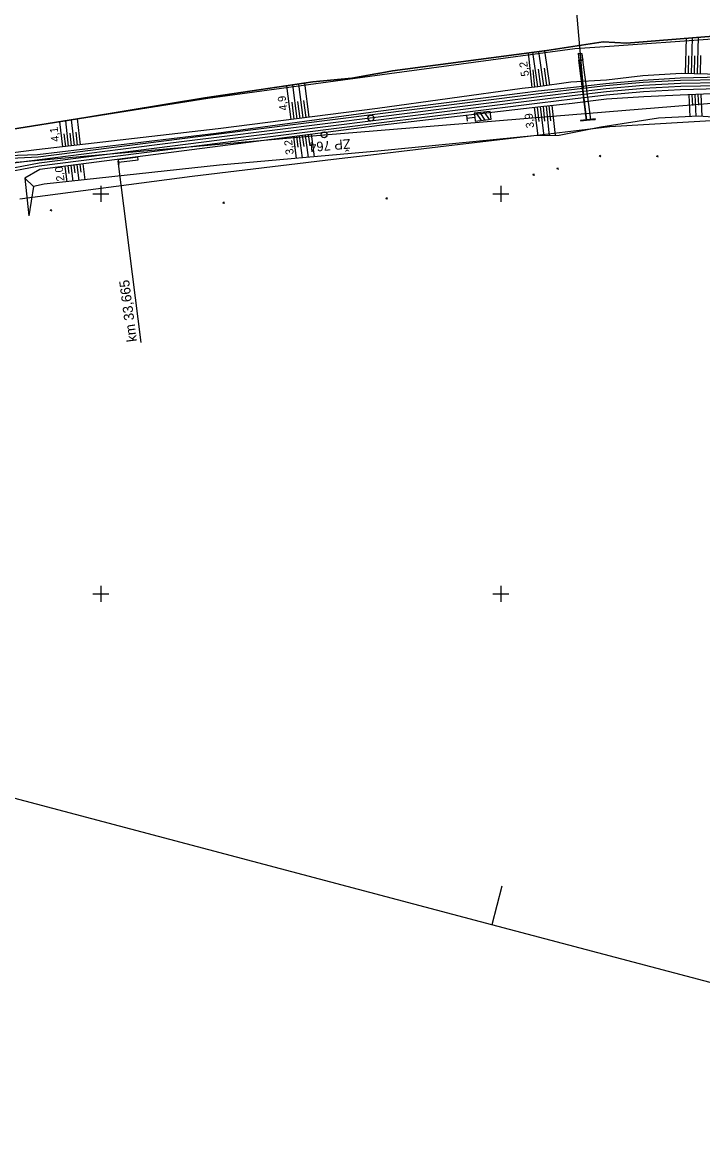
# Model space of a CAD drawing. Extents: x -805011 to -803920, y -1150790 to -1150234.
# Drawn here: x -804519.6 to -804349.5, y -1150736.4 to -1150457.1 of the extents above; entities that cross this region are included whole.
import ezdxf

# ---------------------------------------------------------------- set-up
doc = ezdxf.new("R2010")
doc.units = 0
for name, color, linetype in [('0381KM032-037P - Vrstva 1', 7, 'Continuous'), ('0381KM032-037P - Vrstva 17', 7, 'Continuous'), ('0381KM032-037P - Vrstva 19', 7, 'Continuous'), ('0381KM032-037P - Vrstva 4', 7, 'Continuous'), ('0381KM032-037P - Vrstva 48', 7, 'Continuous'), ('0381KM032-037P - Vrstva 49', 7, 'Continuous'), ('0381KM032-037P - Vrstva 7', 7, 'Continuous'), ('0381KM032-037P - Vrstva 9', 7, 'Continuous'), ('formát', 7, 'Continuous'), ('hran DP - hran DP', 7, 'Continuous'), ('krizky_1000 - Vrstva 1', 7, 'Continuous'), ('vyt_sit - polygon', 7, 'Continuous'), ('vyt_sit - stávající', 7, 'Continuous')]:
    doc.layers.add(name, color=color, linetype=linetype)

msp = doc.modelspace()

# ---------------------------------------------------------------- linework, layer by layer
at = {"layer": '0381KM032-037P - Vrstva 1'}
for points in [[(-804345.19, -1150472.22), (-804355.1, -1150472.39), (-804364.37, -1150472.93), (-804373.68, -1150473.77), (-804382.25, -1150474.73), (-804390.38, -1150475.71), (-804394.38, -1150476.22)], [(-804394.38, -1150476.22), (-804430.66, -1150480.81), (-804470.38, -1150485.81), (-804485.9, -1150487.74)], [(-804485.9, -1150487.74), (-804508.11, -1150490.55), (-804529.67, -1150493.3), (-804537.63, -1150494.31), (-804546.61, -1150495.46), (-804554.2, -1150496.42), (-804564.05, -1150497.67), (-804586.01, -1150500.48), (-804607.92, -1150503.26), (-804630.35, -1150506.11), (-804652.65, -1150508.9), (-804675.7, -1150511.78), (-804698.85, -1150514.71), (-804701.61, -1150515.06), (-804722.18, -1150517.67), (-804729.05, -1150518.54), (-804735.1, -1150519.31), (-804744.56, -1150520.5), (-804767.65, -1150523.46), (-804791, -1150526.42)]]:
    msp.add_lwpolyline(points, dxfattribs=at)
at = {"layer": '0381KM032-037P - Vrstva 17'}
for points in [[(-804368.54, -1150462.33), (-804374.42, -1150462.03), (-804388.45, -1150464.13), (-804427.08, -1150469.25), (-804429.72, -1150469.73), (-804431.75, -1150470.1), (-804437.24, -1150471.08), (-804446.96, -1150472.02), (-804473.97, -1150476), (-804503.76, -1150480.94), (-804524.61, -1150484.28), (-804530.6, -1150485.02), (-804536.33, -1150485.99), (-804541.81, -1150485.21), (-804546.58, -1150482.25), (-804551.41, -1150478.74), (-804558.4, -1150472.14)], [(-804328.85, -1150461.67), (-804338.71, -1150460.38), (-804346.87, -1150460.56), (-804368.54, -1150462.33)]]:
    msp.add_lwpolyline(points, dxfattribs=at)
at = {"layer": '0381KM032-037P - Vrstva 19'}
for p, q in [((-804384.94, -1150412.13), (-804379.37, -1150473.64)), ((-804380.55, -1150464.84), (-804380.55, -1150464.84)), ((-804378.59, -1150481.54), (-804380.47, -1150466.54)), ((-804380.44, -1150466.61), (-804378.59, -1150481.59)), ((-804379.54, -1150466.49), (-804379.54, -1150466.49)), ((-804379.54, -1150466.49), (-804377.61, -1150481.41)), ((-804378.59, -1150481.59), (-804377.64, -1150481.48))]:
    msp.add_line(p, q, dxfattribs=at)
for points in [[(-804380.55, -1150464.84), (-804380.57, -1150464.89), (-804380.47, -1150466.54)], [(-804380.44, -1150466.61), (-804380.55, -1150464.84), (-804379.8, -1150464.93), (-804379.51, -1150466.55)], [(-804379.8, -1150464.93), (-804379.76, -1150464.9), (-804379.54, -1150466.49)], [(-804379.51, -1150466.55), (-804379.54, -1150466.49), (-804380.47, -1150466.54), (-804380.44, -1150466.61), (-804379.51, -1150466.55)], [(-804379.54, -1150466.49), (-804380.47, -1150466.54), (-804380.47, -1150466.54)]]:
    msp.add_lwpolyline(points, dxfattribs=at)
for points in [[(-804380.55, -1150464.84), (-804380.55, -1150464.84)], [(-804378.59, -1150481.54), (-804377.61, -1150481.41), (-804377.64, -1150481.48), (-804376.42, -1150481.39), (-804376.29, -1150481.28), (-804380.1, -1150481.67), (-804380.08, -1150481.76), (-804378.59, -1150481.59)]]:
    msp.add_lwpolyline(points, close=True, dxfattribs=at)
at = {"layer": '0381KM032-037P - Vrstva 4'}
for p, q in [((-804515.79, -1150490.21), (-804529.7, -1150490.74)), ((-804515.61, -1150490.8), (-804529.7, -1150491.57)), ((-804515.43, -1150492.3), (-804529.48, -1150494.97)), ((-804515.43, -1150492.3), (-804515.43, -1150492.3)), ((-804515.37, -1150493.06), (-804529.38, -1150495.79)), ((-804515.37, -1150493.06), (-804515.37, -1150493.06))]:
    msp.add_line(p, q, dxfattribs=at)
for points in [[(-804225.7, -1150511.47), (-804233.93, -1150505.38), (-804241.84, -1150500.35), (-804251.18, -1150495.03), (-804260.27, -1150490.25), (-804271.39, -1150485.02), (-804282.1, -1150481.42), (-804291.28, -1150478.15), (-804302, -1150475.62), (-804311.22, -1150473.82), (-804320.47, -1150472.35), (-804331.17, -1150471.28), (-804341.36, -1150470.84), (-804345.11, -1150470.79), (-804355.15, -1150471.09), (-804364.49, -1150471.64), (-804373.72, -1150472.46), (-804382.56, -1150473.46), (-804390.64, -1150474.3), (-804394.58, -1150474.82), (-804430.68, -1150479.4), (-804471.16, -1150484.87), (-804515.79, -1150490.21)], [(-804222.47, -1150514.31), (-804225.93, -1150511.88), (-804233.81, -1150506.22), (-804242.12, -1150500.85), (-804250.57, -1150495.96), (-804260.44, -1150490.89), (-804271.28, -1150486.07), (-804282.21, -1150481.99), (-804291.28, -1150479.14), (-804302.11, -1150476.36), (-804311.33, -1150474.54), (-804320.55, -1150473.14), (-804330.83, -1150472.06), (-804341.5, -1150471.52), (-804345.16, -1150471.47), (-804355.1, -1150471.64), (-804364.39, -1150472.17), (-804373.73, -1150473.02), (-804382.33, -1150473.97), (-804390.45, -1150474.97), (-804394.45, -1150475.48), (-804430.79, -1150480.07), (-804470.48, -1150485.06), (-804515.61, -1150490.8)], [(-804223.37, -1150515.97), (-804226.85, -1150513.1), (-804234.67, -1150507.48), (-804242.93, -1150502.16), (-804251.31, -1150497.29), (-804261.13, -1150492.25), (-804271.85, -1150487.49), (-804282.71, -1150483.42), (-804291.73, -1150480.59), (-804302.46, -1150477.85), (-804311.66, -1150476.01), (-804320.71, -1150474.65), (-804330.94, -1150473.58), (-804341.55, -1150473.05), (-804345.16, -1150472.99), (-804355.02, -1150473.16), (-804364.28, -1150473.69), (-804373.57, -1150474.51), (-804382.12, -1150475.46), (-804390.26, -1150476.46), (-804394.25, -1150476.96), (-804430.61, -1150481.56), (-804470.33, -1150486.56), (-804515.43, -1150492.3)], [(-804235.83, -1150507.71), (-804243.11, -1150502.63), (-804252.43, -1150497.68), (-804261.4, -1150493.06), (-804272.11, -1150488.47), (-804283.06, -1150484.22), (-804291.82, -1150481.32), (-804302.89, -1150478.85), (-804311.92, -1150476.81), (-804320.92, -1150475.47), (-804331.06, -1150474.34), (-804341.56, -1150473.81), (-804345.45, -1150473.75), (-804355.04, -1150473.96), (-804364.32, -1150474.45), (-804373.64, -1150475.34), (-804382.1, -1150476.35), (-804390.24, -1150477.29), (-804394.24, -1150477.85), (-804430.45, -1150482.3), (-804470.19, -1150487.36), (-804515.37, -1150493.06)]]:
    msp.add_lwpolyline(points, dxfattribs=at)
at = {"layer": '0381KM032-037P - Vrstva 48'}
for p, q in [((-804353.86, -1150469.92), (-804353.59, -1150461.11)), ((-804352.36, -1150469.97), (-804352.08, -1150460.99)), ((-804350.86, -1150470.01), (-804350.58, -1150460.86)), ((-804392.19, -1150473.4), (-804393.06, -1150464.74)), ((-804390.7, -1150473.25), (-804391.97, -1150464.6)), ((-804389.22, -1150473.03), (-804390.48, -1150464.4)), ((-804387.73, -1150472.81), (-804389, -1150464.2)), ((-804353.11, -1150469.95), (-804352.97, -1150465.5)), ((-804351.61, -1150469.99), (-804351.47, -1150465.46)), ((-804350.11, -1150470.04), (-804349.97, -1150465.42)), ((-804391.45, -1150473.33), (-804391.88, -1150468.99)), ((-804389.96, -1150473.14), (-804390.59, -1150468.82)), ((-804388.47, -1150472.92), (-804389.11, -1150468.61)), ((-804452.39, -1150481.41), (-804453.47, -1150472.98)), ((-804450.91, -1150481.22), (-804451.98, -1150472.76)), ((-804449.42, -1150481.03), (-804450.5, -1150472.54)), ((-804447.93, -1150480.84), (-804449.02, -1150472.32)), ((-804352.98, -1150475.24), (-804352.72, -1150480.7)), ((-804352.23, -1150475.2), (-804352.1, -1150477.93)), ((-804351.48, -1150475.16), (-804351.22, -1150480.62)), ((-804350.73, -1150475.13), (-804350.6, -1150477.86)), ((-804349.98, -1150475.09), (-804349.71, -1150480.65)), ((-804451.65, -1150481.31), (-804452.19, -1150477.09)), ((-804450.16, -1150481.12), (-804450.7, -1150476.89)), ((-804448.67, -1150480.93), (-804449.22, -1150476.68)), ((-804391.67, -1150478.44), (-804390.78, -1150485.49)), ((-804390.93, -1150478.35), (-804390.48, -1150481.91)), ((-804390.19, -1150478.25), (-804389.27, -1150485.47)), ((-804389.44, -1150478.17), (-804389.05, -1150481.81)), ((-804388.69, -1150478.09), (-804387.9, -1150485.45)), ((-804387.95, -1150478.01), (-804387.55, -1150481.72)), ((-804387.2, -1150477.93), (-804386.39, -1150485.42)), ((-804508.03, -1150488.07), (-804508.76, -1150481.74)), ((-804506.54, -1150487.9), (-804507.28, -1150481.5)), ((-804505.05, -1150487.73), (-804505.79, -1150481.27)), ((-804509.52, -1150488.25), (-804510.24, -1150481.98)), ((-804505.79, -1150487.81), (-804506.16, -1150484.6)), ((-804508.77, -1150488.16), (-804509.14, -1150485.01)), ((-804507.28, -1150487.99), (-804507.65, -1150484.8)), ((-804451.85, -1150485.69), (-804451.15, -1150491.14)), ((-804451.1, -1150485.59), (-804450.75, -1150488.33)), ((-804450.36, -1150485.49), (-804449.65, -1150491.01)), ((-804449.62, -1150485.4), (-804449.26, -1150488.17)), ((-804448.87, -1150485.3), (-804448.15, -1150490.87)), ((-804448.13, -1150485.21), (-804447.77, -1150488.01)), ((-804447.39, -1150485.11), (-804446.66, -1150490.74)), ((-804508.23, -1150493.02), (-804507.98, -1150494.94)), ((-804507.49, -1150492.92), (-804506.99, -1150496.79)), ((-804506.75, -1150492.83), (-804506.49, -1150494.77)), ((-804506, -1150492.73), (-804505.49, -1150496.63)), ((-804505.26, -1150492.63), (-804505.01, -1150494.59)), ((-804504.52, -1150492.53), (-804504, -1150496.47)), ((-804508.98, -1150493.12), (-804508.48, -1150496.95))]:
    msp.add_line(p, q, dxfattribs=at)
at = {"layer": '0381KM032-037P - Vrstva 49'}
for p, q in [((-804375.44, -1150490.42), (-804374.98, -1150490.64)), ((-804375.1, -1150490.3), (-804375.32, -1150490.76)), ((-804361.14, -1150490.51), (-804360.68, -1150490.73)), ((-804360.8, -1150490.39), (-804361.02, -1150490.85)), ((-804392.06, -1150495.11), (-804391.6, -1150495.33)), ((-804391.72, -1150494.99), (-804391.94, -1150495.45)), ((-804386.04, -1150493.59), (-804385.58, -1150493.81)), ((-804385.7, -1150493.47), (-804385.92, -1150493.93)), ((-804518.94, -1150496.06), (-804516.85, -1150498.14)), ((-804428.79, -1150501.05), (-804428.33, -1150501.27)), ((-804428.45, -1150500.93), (-804428.67, -1150501.39)), ((-804512.71, -1150504), (-804512.25, -1150504.22)), ((-804512.37, -1150503.88), (-804512.59, -1150504.34)), ((-804469.54, -1150502.14), (-804469.08, -1150502.36)), ((-804469.2, -1150502.02), (-804469.42, -1150502.48))]:
    msp.add_line(p, q, dxfattribs=at)
for points in [[(-804541.81, -1150485.21), (-804536.33, -1150485.99), (-804530.6, -1150485.02), (-804524.61, -1150484.28), (-804503.76, -1150480.94), (-804473.97, -1150476), (-804446.96, -1150472.02), (-804437.24, -1150471.08), (-804431.75, -1150470.1), (-804429.72, -1150469.73), (-804427.08, -1150469.25), (-804388.45, -1150464.13), (-804374.42, -1150462.03), (-804368.54, -1150462.33), (-804346.87, -1150460.56), (-804338.71, -1150460.38), (-804328.85, -1150461.67), (-804323.06, -1150462.29), (-804320.34, -1150463.27)], [(-804345.1, -1150470.19), (-804354.95, -1150469.89), (-804364.53, -1150470.46), (-804373.6, -1150471.54), (-804382.52, -1150472.05), (-804390.77, -1150473.26), (-804394.69, -1150473.65), (-804430.78, -1150478.65), (-804470.67, -1150483.74), (-804516.1, -1150489.01), (-804529.7, -1150490.74)], [(-804226.97, -1150514.32), (-804233.94, -1150510.78), (-804236.52, -1150508.57), (-804243.93, -1150503.82), (-804252.72, -1150498.82), (-804262.25, -1150494.6), (-804273.33, -1150489.4), (-804283.59, -1150485.01), (-804292.89, -1150482.47), (-804303.02, -1150479.68), (-804312.2, -1150478.16), (-804321.12, -1150476.62), (-804331.14, -1150475.24), (-804341.8, -1150475.06), (-804345.41, -1150474.87), (-804355.14, -1150475.34), (-804364.22, -1150475.73), (-804373.58, -1150476.33), (-804382.14, -1150477.38), (-804390.01, -1150478.23), (-804394.36, -1150478.78), (-804430.35, -1150482.91), (-804470.16, -1150488.05), (-804515.21, -1150493.93)], [(-804276.15, -1150497.56), (-804284.03, -1150490.16), (-804299.15, -1150485.83), (-804306.89, -1150483.98), (-804317.28, -1150482.7), (-804327.05, -1150481.84), (-804338.6, -1150481.41), (-804350.55, -1150480.59), (-804360.54, -1150481.11), (-804374.96, -1150483.29), (-804385.39, -1150485.41), (-804391.71, -1150485.5), (-804430.73, -1150489.32), (-804470.3, -1150492.85), (-804514.17, -1150497.56)], [(-804515.21, -1150493.93), (-804518.94, -1150496.06), (-804517.94, -1150505.51)], [(-804514.17, -1150497.56), (-804516.85, -1150498.14), (-804517.94, -1150505.51)]]:
    msp.add_lwpolyline(points, dxfattribs=at)
at = {"layer": '0381KM032-037P - Vrstva 7'}
for p, q in [((-804408.58, -1150480.36), (-804408.4, -1150481.84)), ((-804406.13, -1150479.8), (-804404.89, -1150481.66)), ((-804403.9, -1150481.54), (-804405.14, -1150479.68)), ((-804404.15, -1150479.55), (-804402.91, -1150481.41))]:
    msp.add_line(p, q, dxfattribs=at)
msp.add_lwpolyline([(-804408.49, -1150481.1), (-804406.51, -1150480.85), (-804406.38, -1150481.85), (-804402.41, -1150481.35), (-804402.66, -1150479.37), (-804406.63, -1150479.86), (-804406.51, -1150480.85)], dxfattribs=at)
msp.add_circle((-804432.47, -1150481.04), 0.75, dxfattribs=at)
at = {"layer": '0381KM032-037P - Vrstva 9'}
for p, q in [((-804490.7, -1150490.86), (-804495.66, -1150491.5)), ((-804495.66, -1150491.5), (-804495.58, -1150492.1)), ((-804489.86, -1150537.15), (-804495.62, -1150491.8)), ((-804495.58, -1150492.1), (-804490.62, -1150491.45)), ((-804495.58, -1150492.1), (-804495.5, -1150492.69)), ((-804490.62, -1150491.45), (-804490.7, -1150490.86))]:
    msp.add_line(p, q, dxfattribs=at)
at = {"layer": 'formát'}
for p, q in [((-804402.28, -1150682.7), (-805011.32, -1150521.54)), ((-804399.72, -1150673.03), (-804402.28, -1150682.7)), ((-804399.72, -1150673.03), (-804402.28, -1150682.7)), ((-804199.27, -1150736.42), (-804402.28, -1150682.7))]:
    msp.add_line(p, q, dxfattribs=at)
at = {"layer": 'hran DP - hran DP'}
for p, q in [((-804374.01, -1150463.14), (-804345.91, -1150461.18)), ((-804427.86, -1150469.92), (-804381.52, -1150463.67)), ((-804381.52, -1150463.67), (-804374.01, -1150463.14)), ((-804473.24, -1150476.04), (-804427.86, -1150469.92)), ((-804532.83, -1150485.53), (-804473.24, -1150476.04)), ((-804340.86, -1150481.33), (-804372.75, -1150483.24)), ((-804383.87, -1150484.55), (-804413.66, -1150488.07)), ((-804372.75, -1150483.24), (-804383.87, -1150484.55)), ((-804413.66, -1150488.07), (-804432.51, -1150490.32)), ((-804441.78, -1150491.42), (-804477.16, -1150495.64)), ((-804432.51, -1150490.32), (-804441.78, -1150491.42)), ((-804477.16, -1150495.64), (-804520.26, -1150501.29))]:
    msp.add_line(p, q, dxfattribs=at)
at = {"layer": 'krizky_1000 - Vrstva 1'}
for points in [[(-804500, -1150498), (-804500, -1150502)], [(-804400, -1150498), (-804400, -1150502)], [(-804502, -1150500), (-804498, -1150500)], [(-804402, -1150500), (-804398, -1150500)], [(-804500, -1150598), (-804500, -1150602)], [(-804400, -1150598), (-804400, -1150602)], [(-804502, -1150600), (-804498, -1150600)], [(-804402, -1150600), (-804398, -1150600)]]:
    msp.add_lwpolyline(points, dxfattribs=at)
at = {"layer": 'vyt_sit - polygon'}
for p, q in [((-804444.16, -1150485.23), (-804328.27, -1150475.77)), ((-804594.75, -1150498.6), (-804444.16, -1150485.23))]:
    msp.add_line(p, q, dxfattribs=at)
at = {"layer": 'vyt_sit - stávající'}
msp.add_line((-804444.21, -1150485.23), (-804444.1, -1150485.23), dxfattribs=at)
msp.add_circle((-804444.16, -1150485.23), 0.756, dxfattribs=at)

# ---------------------------------------------------------------- texts
at = {"layer": '0381KM032-037P - Vrstva 48'}
for s, rotation, p in [('5,2', 97.5493, (-804392.93, -1150470.51)), ('4,9', 98.3966, (-804453.3, -1150479.03)), ('3,9', 97.2061, (-804391.65, -1150483.43)), ('4,1', 96.6169, (-804510.37, -1150486.87)), ('3,2', 97.3569, (-804451.73, -1150490.07)), ('2,0', 97.4363, (-804509.04, -1150496.72))]:
    msp.add_text(s, height=2, rotation=rotation, dxfattribs=at).set_placement(p)
at = {"layer": '0381KM032-037P - Vrstva 9'}
msp.add_text('km 33,665', height=2.5, rotation=97.4056, dxfattribs=at).set_placement((-804490.93, -1150536.84))
at = {"layer": 'vyt_sit - stávající'}
msp.add_text('ŽP 764', height=2.4, rotation=185, dxfattribs=at).set_placement((-804437.66, -1150486.27))

doc.saveas('drawing.dxf')
